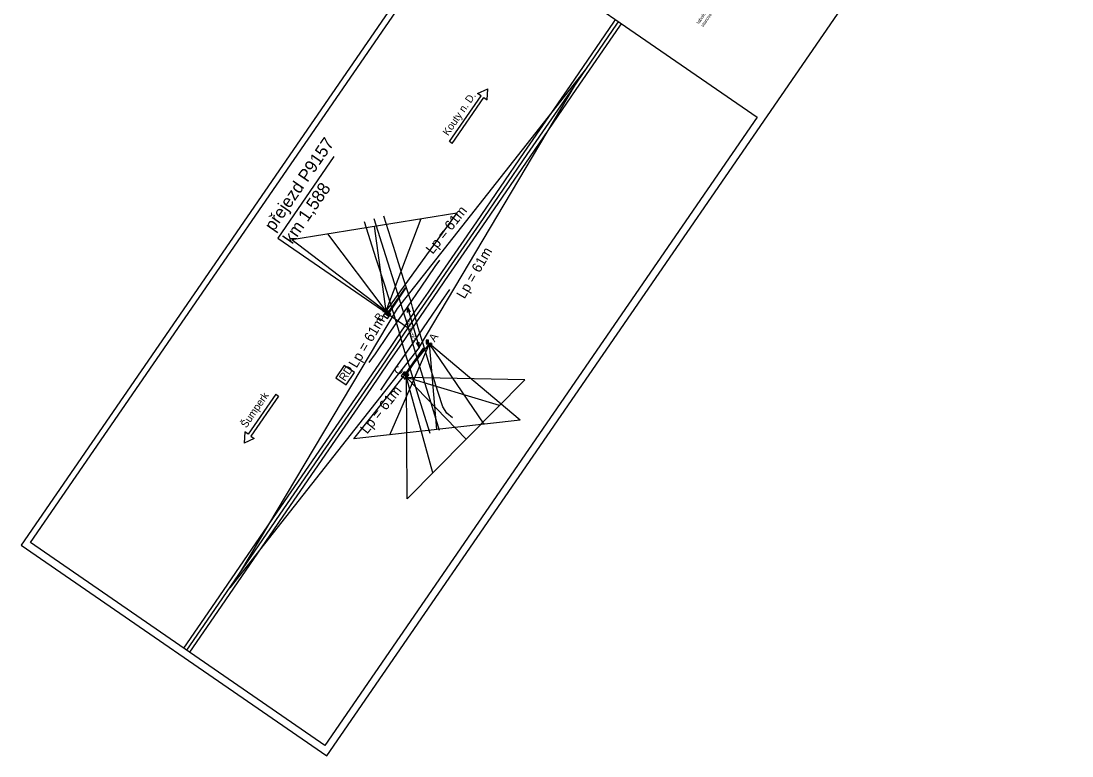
# Model space of a CAD drawing. Extents: x -558217 to -558007, y -1073488 to -1073229.
# Drawn here: x -558216.6 to -558006.5, y -1073487.6 to -1073340.9 of the extents above; entities that cross this region are included whole.
import ezdxf

# ---------------------------------------------------------------- set-up
doc = ezdxf.new("R2010")
doc.units = 0
for name, color, linetype in [('Default', 7, 'Continuous'), ('El2015-Zabzař nadzemní', 7, 'Continuous'), ('Kolej', 7, 'Continuous'), ('nové prvky ZZ', 7, 'Continuous'), ('PS01_PS02_nové prvky ZZ', 7, 'Continuous'), ('Přejezd - štěrkové lože', 7, 'Continuous'), ('Rámeček', 7, 'Continuous'), ('Rámeček stavby', 7, 'Continuous'), ('Stavba', 7, 'Continuous')]:
    doc.layers.add(name, color=color, linetype=linetype)

msp = doc.modelspace()

# ---------------------------------------------------------------- linework, layer by layer
at = {"layer": 'Default'}
for p, q in [((-558141.36, -1073398.29), (-558103.51, -1073350.28)), ((-558137.01, -1073406.08), (-558105.76, -1073353.54)), ((-558125.32, -1073355.32), (-558123.27, -1073354.41)), ((-558123.41, -1073356.63), (-558123.27, -1073354.41)), ((-558130.92, -1073364.94), (-558124.62, -1073355.8)), ((-558130.39, -1073365.31), (-558124.09, -1073356.17)), ((-558124.62, -1073355.8), (-558125.32, -1073355.32)), ((-558124.09, -1073356.17), (-558123.41, -1073356.63)), ((-558130.39, -1073365.31), (-558130.92, -1073364.94)), ((-558162.47, -1073384.53), (-558129.48, -1073379.19)), ((-558129.48, -1073379.19), (-558143.67, -1073398.84)), ((-558136.65, -1073380.35), (-558143.67, -1073398.84)), ((-558145.97, -1073381.86), (-558143.67, -1073398.84)), ((-558162.47, -1073384.53), (-558143.67, -1073398.84)), ((-558155.33, -1073383.38), (-558143.67, -1073398.84)), ((-558172.63, -1073450.82), (-558141.36, -1073398.29)), ((-558139.36, -1073398.02), (-558137.01, -1073406.08)), ((-558150.05, -1073424.32), (-558134.93, -1073405.37)), ((-558142.83, -1073423.5), (-558134.93, -1073405.37)), ((-558133.45, -1073422.44), (-558134.93, -1073405.37)), ((-558124.02, -1073421.37), (-558134.93, -1073405.37)), ((-558116.84, -1073420.56), (-558134.93, -1073405.37)), ((-558137.01, -1073406.08), (-558174.87, -1073454.08)), ((-558134.28, -1073431.12), (-558139.5, -1073412.04)), ((-558139.37, -1073436.28), (-558139.5, -1073412.04)), ((-558120.96, -1073417.64), (-558139.5, -1073412.04)), ((-558127.63, -1073424.39), (-558139.5, -1073412.04)), ((-558115.88, -1073412.5), (-558139.5, -1073412.04)), ((-558115.88, -1073412.5), (-558139.37, -1073436.28)), ((-558165.67, -1073415.39), (-558171.19, -1073423.39)), ((-558165.14, -1073415.76), (-558170.65, -1073423.76)), ((-558165.67, -1073415.39), (-558165.14, -1073415.76)), ((-558116.84, -1073420.56), (-558150.05, -1073424.32)), ((-558171.86, -1073422.93), (-558172, -1073425.15)), ((-558169.95, -1073424.25), (-558172, -1073425.15)), ((-558171.19, -1073423.39), (-558171.86, -1073422.93)), ((-558170.65, -1073423.76), (-558169.95, -1073424.25))]:
    msp.add_line(p, q, dxfattribs=at)
for points in [[(-558132.91, -1073422.64), (-558135.07, -1073415.67), (-558136.57, -1073410.83), (-558138.15, -1073405.73), (-558139.25, -1073401.67), (-558140.3, -1073398.33), (-558141.91, -1073393.21), (-558143.65, -1073387.75), (-558146.01, -1073380.39)], [(-558130.33, -1073420.15), (-558131.49, -1073419.21), (-558132.27, -1073417.93), (-558133.17, -1073415.08), (-558134.7, -1073410.17), (-558136.19, -1073405.35), (-558137.19, -1073402.13), (-558138.3, -1073398.04), (-558138.62, -1073396.92), (-558140.03, -1073392.59), (-558141.45, -1073388.09), (-558141.74, -1073387.17), (-558144.08, -1073379.87)], [(-558134.82, -1073423.23), (-558136.98, -1073416.27), (-558138.48, -1073411.42), (-558140.07, -1073406.28), (-558141.17, -1073402.24), (-558142.21, -1073398.93), (-558143.82, -1073393.81), (-558145.56, -1073388.36), (-558147.91, -1073380.99)], [(-558141.36, -1073398.31), (-558141.37, -1073398.27)], [(-558139.32, -1073399.1), (-558139.36, -1073398.02), (-558138.82, -1073398.96)], [(-558137.06, -1073405), (-558137.01, -1073406.08), (-558137.56, -1073405.14)], [(-558137.01, -1073406.1), (-558137.02, -1073406.06)]]:
    msp.add_lwpolyline(points, dxfattribs=at)
at = {"layer": 'Kolej'}
for points in [[(-558167.24, -1073441.68), (-558165.37, -1073438.97), (-558156.25, -1073425.72), (-558147.81, -1073413.44), (-558144.29, -1073408.32), (-558141.65, -1073404.49), (-558137.9, -1073399.03), (-558135.16, -1073395.05), (-558132.31, -1073390.9), (-558125.49, -1073380.97), (-558115.99, -1073367.15), (-558106.78, -1073353.75), (-558098.08, -1073341.1), (-558097.74, -1073340.6)], [(-558166.64, -1073442.09), (-558164.78, -1073439.38), (-558155.66, -1073426.13), (-558147.22, -1073413.85), (-558143.69, -1073408.73), (-558141.06, -1073404.9), (-558137.3, -1073399.44), (-558134.57, -1073395.46), (-558131.72, -1073391.31), (-558124.89, -1073381.38), (-558115.4, -1073367.56), (-558106.18, -1073354.16), (-558097.49, -1073341.51), (-558097.14, -1073341.01)], [(-558166.05, -1073442.5), (-558164.18, -1073439.79), (-558155.07, -1073426.54), (-558146.62, -1073414.26), (-558143.1, -1073409.14), (-558140.47, -1073405.31), (-558136.71, -1073399.85), (-558133.97, -1073395.87), (-558131.12, -1073391.72), (-558124.3, -1073381.78), (-558114.81, -1073367.97), (-558105.59, -1073354.57), (-558096.89, -1073341.92), (-558096.55, -1073341.42)], [(-558166.05, -1073442.5), (-558164.18, -1073439.79), (-558155.07, -1073426.54), (-558146.62, -1073414.26), (-558143.1, -1073409.14), (-558140.47, -1073405.31), (-558136.71, -1073399.85), (-558133.97, -1073395.87), (-558131.12, -1073391.72), (-558124.3, -1073381.78), (-558114.81, -1073367.97), (-558105.59, -1073354.57), (-558096.89, -1073341.92), (-558096.55, -1073341.42)], [(-558146.98, -1073409.1), (-558145.75, -1073407.31), (-558143.12, -1073403.49), (-558139.36, -1073398.02), (-558136.63, -1073394.05), (-558133.78, -1073389.89), (-558132.89, -1073388.61)], [(-558144.68, -1073414.57), (-558141.63, -1073410.14), (-558139, -1073406.32), (-558135.24, -1073400.85), (-558132.51, -1073396.88), (-558130.85, -1073394.46)], [(-558141.38, -1073398.31), (-558141.35, -1073398.26)], [(-558137.02, -1073406.09), (-558137, -1073406.06)], [(-558184.02, -1073466.12), (-558178.45, -1073458.02), (-558167.22, -1073441.68)], [(-558183.42, -1073466.53), (-558177.86, -1073458.42), (-558166.63, -1073442.09)], [(-558182.83, -1073466.94), (-558177.26, -1073458.83), (-558166.03, -1073442.5)], [(-558182.83, -1073466.94), (-558177.26, -1073458.83), (-558166.03, -1073442.5)]]:
    msp.add_lwpolyline(points, dxfattribs=at)
at = {"layer": 'nové prvky ZZ'}
for p, q in [((-558139.82, -1073394.15), (-558143.25, -1073399.08)), ((-558139.73, -1073394.22), (-558143.08, -1073399.19)), ((-558139.73, -1073394.22), (-558139.82, -1073394.15)), ((-558143.08, -1073398.76), (-558144.27, -1073398.93)), ((-558143.33, -1073399.38), (-558143.66, -1073398.94)), ((-558143.08, -1073399.19), (-558143.25, -1073399.08)), ((-558135.53, -1073405.42), (-558134.34, -1073405.31)), ((-558135.38, -1073404.94), (-558134.94, -1073405.27)), ((-558136.23, -1073406.21), (-558139.65, -1073411.14)), ((-558136.14, -1073406.28), (-558139.48, -1073411.26)), ((-558136.14, -1073406.28), (-558136.23, -1073406.21)), ((-558139.93, -1073412.45), (-558139.07, -1073411.62)), ((-558139.73, -1073411.44), (-558139.57, -1073411.97)), ((-558139.48, -1073411.26), (-558139.65, -1073411.14))]:
    msp.add_line(p, q, dxfattribs=at)
for points in [[(-558143.38, -1073399.34), (-558143.76, -1073399.08), (-558144.17, -1073399.68), (-558143.31, -1073400.27), (-558142.89, -1073399.67), (-558143.27, -1073399.41)], [(-558143.38, -1073399.34), (-558143.76, -1073399.08), (-558143.56, -1073398.79), (-558143.07, -1073399.01), (-558142.7, -1073399.39), (-558142.89, -1073399.67), (-558143.27, -1073399.41)], [(-558139.79, -1073411.4), (-558140.16, -1073411.14), (-558140.57, -1073411.74), (-558139.71, -1073412.34), (-558139.3, -1073411.74), (-558139.67, -1073411.48)], [(-558139.79, -1073411.4), (-558140.16, -1073411.14), (-558139.97, -1073410.85), (-558139.48, -1073411.07), (-558139.1, -1073411.45), (-558139.3, -1073411.74), (-558139.67, -1073411.48)]]:
    msp.add_lwpolyline(points, dxfattribs=at)
for points in [[(-558143.38, -1073398.8), (-558143.4, -1073398.98), (-558143.9, -1073399.06), (-558143.97, -1073398.88)], [(-558142.93, -1073399.38), (-558143.47, -1073399.01), (-558143.72, -1073399.38), (-558143.19, -1073399.75)], [(-558143.03, -1073399.3), (-558143.39, -1073399.06), (-558143.64, -1073399.43), (-558143.29, -1073399.68)], [(-558135.6, -1073404.61), (-558135.6, -1073405.26), (-558135.15, -1073405.26), (-558135.15, -1073404.61)], [(-558135.6, -1073404.74), (-558135.6, -1073405.16), (-558135.15, -1073405.16), (-558135.15, -1073404.73)], [(-558135.23, -1073405.39), (-558135.2, -1073405.21), (-558134.7, -1073405.16), (-558134.63, -1073405.34)], [(-558139.33, -1073411.45), (-558139.86, -1073411.07), (-558140.13, -1073411.43), (-558139.6, -1073411.81)], [(-558139.44, -1073411.38), (-558139.78, -1073411.13), (-558140.04, -1073411.49), (-558139.7, -1073411.74)], [(-558139.72, -1073412.24), (-558139.81, -1073412.08), (-558139.44, -1073411.73), (-558139.28, -1073411.83)]]:
    msp.add_lwpolyline(points, close=True, dxfattribs=at)
for centre in [(-558143.33, -1073399.38), (-558143.33, -1073399.38), (-558143.33, -1073399.38), (-558135.38, -1073404.94), (-558135.38, -1073404.94), (-558135.38, -1073404.94), (-558139.73, -1073411.44), (-558139.73, -1073411.44), (-558139.73, -1073411.44)]:
    msp.add_circle(centre, 0.0675, dxfattribs=at)
at = {"layer": 'Přejezd - štěrkové lože'}
for p, q in [((-558154.08, -1073367.92), (-558165.28, -1073384.22)), ((-558165.28, -1073384.22), (-558139.18, -1073402.17))]:
    msp.add_line(p, q, dxfattribs=at)
at = {"layer": 'Rámeček'}
msp.add_lwpolyline([(-558006.52, -1073271.47), (-558067.67, -1073229.35), (-558216.58, -1073445.53), (-558155.43, -1073487.65)], close=True, dxfattribs=at)
at = {"layer": 'Rámeček stavby'}
msp.add_lwpolyline([(-558128.28, -1073319.56), (-558069.44, -1073360.09), (-558155.85, -1073485.53), (-558214.69, -1073445)], close=True, dxfattribs=at)
at = {"layer": 'Stavba'}
msp.add_lwpolyline([(-558152.01, -1073409.67), (-558153.68, -1073412.13), (-558151.6, -1073413.53), (-558149.93, -1073411.05), (-558152.01, -1073409.67)], dxfattribs=at)

# ---------------------------------------------------------------- texts
at = {"layer": 'Default'}
for s, height, rotation, p in [('tabulek normy ČSN 73 6380. Rozhledové poměry na přejezdu vyhovují této', 0.66, 55.4593, (-558081.11, -1073341.53)), ('stanovené délce.', 0.66, 55.4593, (-558080.21, -1073342.15)), ('Kouty n. D.', 1.5, 55.4307, (-558131.2, -1073363.91)), ('Dp=8,4m', 0.8, 106.3103, (-558137.72, -1073404.7)), ('Šumperk', 1.5, 55.4307, (-558171.54, -1073422.26))]:
    msp.add_text(s, height=height, rotation=rotation, dxfattribs=at).set_placement(p)
at = {"layer": 'El2015-Zabzař nadzemní'}
msp.add_text('RD', height=1.6, rotation=56.3993, dxfattribs=at).set_placement((-558151.83, -1073412.95))
at = {"layer": 'PS01_PS02_nové prvky ZZ'}
for s, height, rotation, p in [('Lp = 61m', 2, 51.4442, (-558134.3, -1073387.57)), ('Lp = 61m', 2, 59.9286, (-558127.94, -1073396.5)), ('B', 1.6, 53.0599, (-558144.78, -1073401.04)), ('Lp = 61m', 2, 59.2711, (-558149.52, -1073410.31)), ('A', 1.6, 55.7527, (-558133.9, -1073405.07)), ('C', 1.6, 55.7527, (-558140.88, -1073411.71)), ('Lp = 61m', 2, 51.2256, (-558147.41, -1073423.47))]:
    msp.add_text(s, height=height, rotation=rotation, dxfattribs=at).set_placement(p)
at = {"layer": 'Přejezd - štěrkové lože'}
for s, p in [('přejezd P9157', (-558166.07, -1073383.03)), ('km 1,588', (-558162.36, -1073385.58))]:
    msp.add_text(s, height=2.5, rotation=55.491, dxfattribs=at).set_placement(p)

doc.saveas('drawing.dxf')
